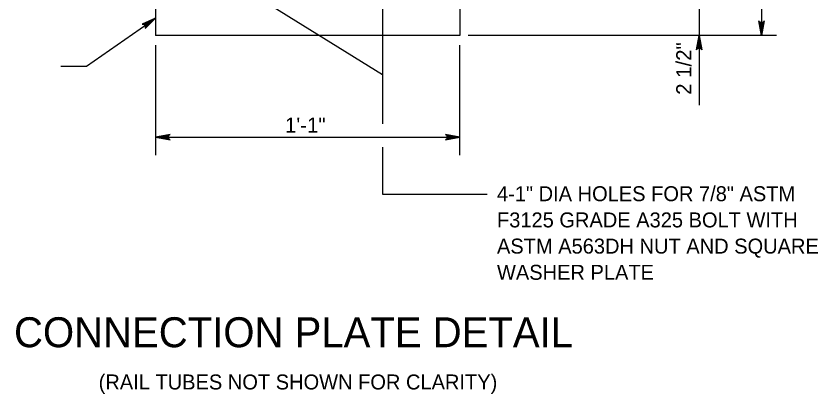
# Model space of a CAD drawing. Extents: x 632007860 to 635435983, y 295418622 to 297794622.
# Drawn here: x 634198631 to 634361717, y 295768013 to 295844947 of the extents above; entities that cross this region are included whole.
import ezdxf

# ---------------------------------------------------------------- set-up
doc = ezdxf.new("R2010")
doc.units = 0
for name, color, linetype in [('S-DETL-DIMS', 7, 'Continuous'), ('S-DETL-T120', 7, 'Continuous'), ('S-DETL-T240', 7, 'Continuous'), ('S-STEL', 7, 'Continuous')]:
    doc.layers.add(name, color=color, linetype=linetype)

msp = doc.modelspace()

# ---------------------------------------------------------------- linework, layer by layer
at = {"layer": 'S-DETL-DIMS'}
for p, q in [((634337544, 295954211), (634337544, 295826801)), ((634350238, 295937436), (634350238, 295841001)), ((634243282, 295851598), (634273162, 295833077)), ((634212941, 295834726), (634227006, 295844537)), ((634353314, 295841001), (634290560, 295841001)), ((634227006, 295839048), (634227006, 295816605)), ((634288915, 295816605), (634288915, 295839048)), ((634207708, 295834726), (634212941, 295834726)), ((634227006, 295820308), (634288915, 295820308))]:
    msp.add_line(p, q, dxfattribs=at)
for points in [[(634273162, 295866774), (634273162, 295823010)], [(634227006, 295844537), (634224261, 295843299), (634224400, 295843300), (634224539, 295843300), (634224644, 295843252), (634224748, 295843205), (634224819, 295843133), (634224890, 295843061), (634224933, 295842970), (634224976, 295842879), (634224984, 295842764), (634224993, 295842649), (634224944, 295842519), (634224896, 295842389), (634227006, 295844537), (634224944, 295842519), (634224993, 295842649), (634227006, 295844537), (634224984, 295842764), (634224976, 295842879), (634227006, 295844537), (634224933, 295842970), (634224890, 295843061), (634227006, 295844537), (634224819, 295843133), (634224748, 295843205), (634227006, 295844537), (634224644, 295843252), (634224539, 295843300), (634227006, 295844537), (634224400, 295843300)], [(634350238, 295841001), (634349683, 295843960), (634349762, 295843846), (634349841, 295843732), (634349940, 295843674), (634350039, 295843615), (634350138, 295843598), (634350238, 295843581), (634350337, 295843598), (634350436, 295843615), (634350535, 295843674), (634350635, 295843732), (634350714, 295843846), (634350793, 295843960), (634350238, 295841001), (634350714, 295843846), (634350635, 295843732), (634350238, 295841001), (634350535, 295843674), (634350436, 295843615), (634350238, 295841001), (634350337, 295843598), (634350238, 295843581), (634350238, 295841001), (634350138, 295843598), (634350039, 295843615), (634350238, 295841001), (634349940, 295843674), (634349841, 295843732), (634350238, 295841001), (634349762, 295843846)], [(634337544, 295841001), (634338099, 295838042), (634338020, 295838156), (634337941, 295838270), (634337841, 295838329), (634337742, 295838387), (634337643, 295838404), (634337544, 295838421), (634337445, 295838404), (634337345, 295838387), (634337246, 295838329), (634337147, 295838270), (634337068, 295838156), (634336989, 295838042), (634337544, 295841001), (634337068, 295838156), (634337147, 295838270), (634337544, 295841001), (634337246, 295838329), (634337345, 295838387), (634337544, 295841001), (634337445, 295838404), (634337544, 295838421), (634337544, 295841001), (634337643, 295838404), (634337742, 295838387), (634337544, 295841001), (634337841, 295838329), (634337941, 295838270), (634337544, 295841001), (634338020, 295838156)], [(634227006, 295820308), (634229965, 295819753), (634229851, 295819832), (634229737, 295819911), (634229678, 295820011), (634229619, 295820110), (634229602, 295820209), (634229585, 295820308), (634229602, 295820407), (634229619, 295820507), (634229678, 295820606), (634229737, 295820705), (634229851, 295820784), (634229965, 295820863), (634227006, 295820308), (634229851, 295820784), (634229737, 295820705), (634227006, 295820308), (634229678, 295820606), (634229619, 295820507), (634227006, 295820308), (634229602, 295820407), (634229585, 295820308), (634227006, 295820308), (634229602, 295820209), (634229619, 295820110), (634227006, 295820308), (634229678, 295820011), (634229737, 295819911), (634227006, 295820308), (634229851, 295819832)], [(634288915, 295820308), (634285955, 295820863), (634286069, 295820784), (634286183, 295820705), (634286242, 295820606), (634286301, 295820507), (634286318, 295820407), (634286335, 295820308), (634286318, 295820209), (634286301, 295820110), (634286242, 295820011), (634286183, 295819911), (634286069, 295819832), (634285955, 295819753), (634288915, 295820308), (634286069, 295819832), (634286183, 295819911), (634288915, 295820308), (634286242, 295820011), (634286301, 295820110), (634288915, 295820308), (634286318, 295820209), (634286335, 295820308), (634288915, 295820308), (634286318, 295820407), (634286301, 295820507), (634288915, 295820308), (634286242, 295820606), (634286183, 295820705), (634288915, 295820308), (634286069, 295820784)], [(634273162, 295818252), (634273162, 295808681), (634294425, 295808681)]]:
    msp.add_lwpolyline(points, dxfattribs=at)
at = {"layer": 'S-STEL'}
for p, q in [((634227006, 295946369), (634227006, 295841001)), ((634288915, 295946369), (634288915, 295841001)), ((634288915, 295841001), (634227006, 295841001))]:
    msp.add_line(p, q, dxfattribs=at)

# ---------------------------------------------------------------- texts
at = {"layer": 'S-DETL-T120'}
msp.add_text('2 1/2"', height=3102.3, rotation=90, dxfattribs=at).set_placement((634335989, 295828906))
for s, height, p in [('1\'-1"', 3102.2, (634253331, 295821182)), ('4-1" DIA HOLES FOR 7/8" ASTM', 3048.01, (634296439, 295807254)), ('F3125 GRADE A325 BOLT WITH ', 3048.01, (634296439, 295801920)), ('ASTM A563DH NUT AND SQUARE ', 3048.01, (634296439, 295796586)), ('WASHER PLATE', 3048.01, (634296439, 295791252)), ('(RAIL TUBES NOT SHOWN FOR CLARITY)', 3048.01, (634215433, 295768930))]:
    msp.add_text(s, height=height, dxfattribs=at).set_placement(p)
at = {"layer": 'S-DETL-T240'}
msp.add_text('CONNECTION PLATE DETAIL', height=6096, dxfattribs=at).set_placement((634198217, 295777532))

doc.saveas('drawing.dxf')
